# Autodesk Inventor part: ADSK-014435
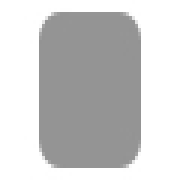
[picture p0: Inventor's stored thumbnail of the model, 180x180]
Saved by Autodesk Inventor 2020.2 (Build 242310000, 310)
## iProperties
IsCustomPart: 1
Created: 2019-01
Part Number: ADSK-014435
Material: Stahl, weich
Document SubType Name: Modeling
Designer: lutzd
Language: de-DE
Size Designation: 5 x 40 x 40
Categories: <MemberInstance><Categories><Category DisplayName="Sonstige Bauteile" InternalName="5aa15e00-363f-49f2-933f-16f664388e3f" Mnemonic="OTHER"><Category DisplayName
Mass: 61.9577 g
Surface Area: 39.1416 cm^2
Volume: 7.8927 cm^3
Density: 7.85 g/cm^3
Appearance: Semi-Polished(8)
Mass: 0,062 kg
VLT_Material: Stahl, weich
DocNumber: ADSK-014435
Folder: 01 - Themengebiete\Simplification\01 - Packaging machine\500666L\Frame\
VDS_Category: 3D Komponenten
VDS_NumSchm: Autodesk
Dimensions: 40x5x40 mm
Title: end cap
Author: lutzd
Revision Number: -
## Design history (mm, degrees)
sketch "Sketch1"
  geometry: L1 (0, 20.175)-(0, -21.446); L2 (-20.203, 0)-(20.169, 0); L3 (-20, 20)-(20, 20); L4 (20, 20)-(20, -20); L5 (20, -20)-(-20, -20); L6 (-20, -20)-(-20, 20); 1 further point
  constraints: 12 end point, 2 horizontal, 2 parallel, 2 point on line, 1 perpendicular, 1 vertical
  dimensions: "d0" = 40 distance between parallel lines of L5 L3 (= height); "d1" = 20 distance between parallel lines of L2 L3 (= 0.5 x height); "d2" = 40 distance between parallel lines of L6 L4 (= width); "d3" = 20 distance between parallel lines of L6 L1 (= 0.5 x width)
extrude "Extrusion1" new body sketch "Sketch1" distance "d4" = 5 (= thickness); taper "d5" = 0 deg
fillet "Fillet1" dims "d6" = 5 (= fillet), "d7" = 0, "fillet" = 5 [user parameter; used in 1 equation term]
chamfer "Chamfer1" distance "d8" = 0 (computed from chamfer); stored, may be unused: second distance "d9" = 2, angle "d10" = 45 deg; dims "d11" = 0, "chamfer" = 0 [user parameter; used in 1 equation term]
body "Solid1"
other parameters: "thickness" = 5 [user parameter; used in 1 equation term], "width" = 40 [user parameter; used in 2 equation terms], "height" = 40 [user parameter; used in 2 equation terms]
